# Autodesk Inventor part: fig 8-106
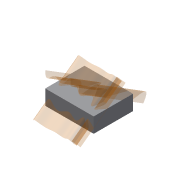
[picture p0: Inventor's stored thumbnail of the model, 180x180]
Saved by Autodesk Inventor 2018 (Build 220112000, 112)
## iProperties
Shininess: 64.0
Length Units: 11269
Angle Units: 11279
Time Units: 11290
Mass Units: 11283
Length Display Precision: 3
Angle Display Precision: 2
Compacted: True
Part Number: fig 8-106
Document SubType Name: Modeling
Created: 2002-12
Designer: deepak
Density: 1 g/cm^3
Material: Generic
Appearance: Default
Density: 0.0
Volumn: 0.0
Area: 0.0
PropertySet Name: Model Information
Control State: 0
Master: False
Checked Out: False
Author: deepak
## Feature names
1. Extrusion1
## Parameters: d1 = 0, d2 = 0, d3 = 0, d4 = 0, d5 = 0
